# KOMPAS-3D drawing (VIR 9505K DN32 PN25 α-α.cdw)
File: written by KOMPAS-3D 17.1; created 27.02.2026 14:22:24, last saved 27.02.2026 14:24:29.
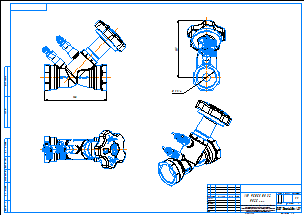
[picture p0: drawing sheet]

Sheet 1: A2, landscape

Title block, sheet 1: name: VIR 9505K DN32 / PN25 р-р; material: Внимание! Данный продукт является объектом авторского права ООО «Торговый Дом АДЛ». / Запрещается изменение, копирование, распространение / (в том числе путем копирования на другие сайты и ресурсы в Интернете) / или любое иное использование информации и объектов без предварительного / согласия правообладателя (ООО «Торговый Дом АДЛ»).; sheets: 1; organisation: ООО "Торговый дом АДЛ"; sheet format: A2

Views: Вид 1, Спереди, Проекционный вид 2, Проекционный вид 3, Вид 4, Изометрия
Referenced files in C:\Users\mipv\Desktop\VIR 9505K STP формат\: VIR 9505K DN32 PN25 р-р.m3d
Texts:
  adm
Dimensions and other numbers on the sheet: 112; 122; 1:1; 1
